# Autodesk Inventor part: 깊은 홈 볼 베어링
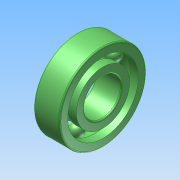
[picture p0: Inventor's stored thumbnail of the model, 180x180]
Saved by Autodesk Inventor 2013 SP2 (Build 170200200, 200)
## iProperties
Created: 2026-07
Part Number: 깊은 홈 볼 베어링
Material: Generic
Document SubType Name: Modeling
Designer: a
Density: 1 g/cm^3
Author: a
변환 표준: STEP AP214IS
전처리기: Build: 200, Release: 2013 SP2 Update 6 - Date: Thu 07/17/2014
전송 단위: 밀리미터
불확실성: 0.01
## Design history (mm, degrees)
node "깊은 홈 볼 베어링 62031"
body "Solid1"
node "Solid1_1"
node "Solid1_2"
node "Solid1_3"
node "Solid1_4"
node "Solid1_5"
node "Solid1_6"
node "Solid1_7"
node "Solid1_8"
node "기준1"
node "기준2"
node "기준3"
node "기준4"
node "기준5"
node "기준6"
node "기준7"
node "기준8"
node "기준9"
